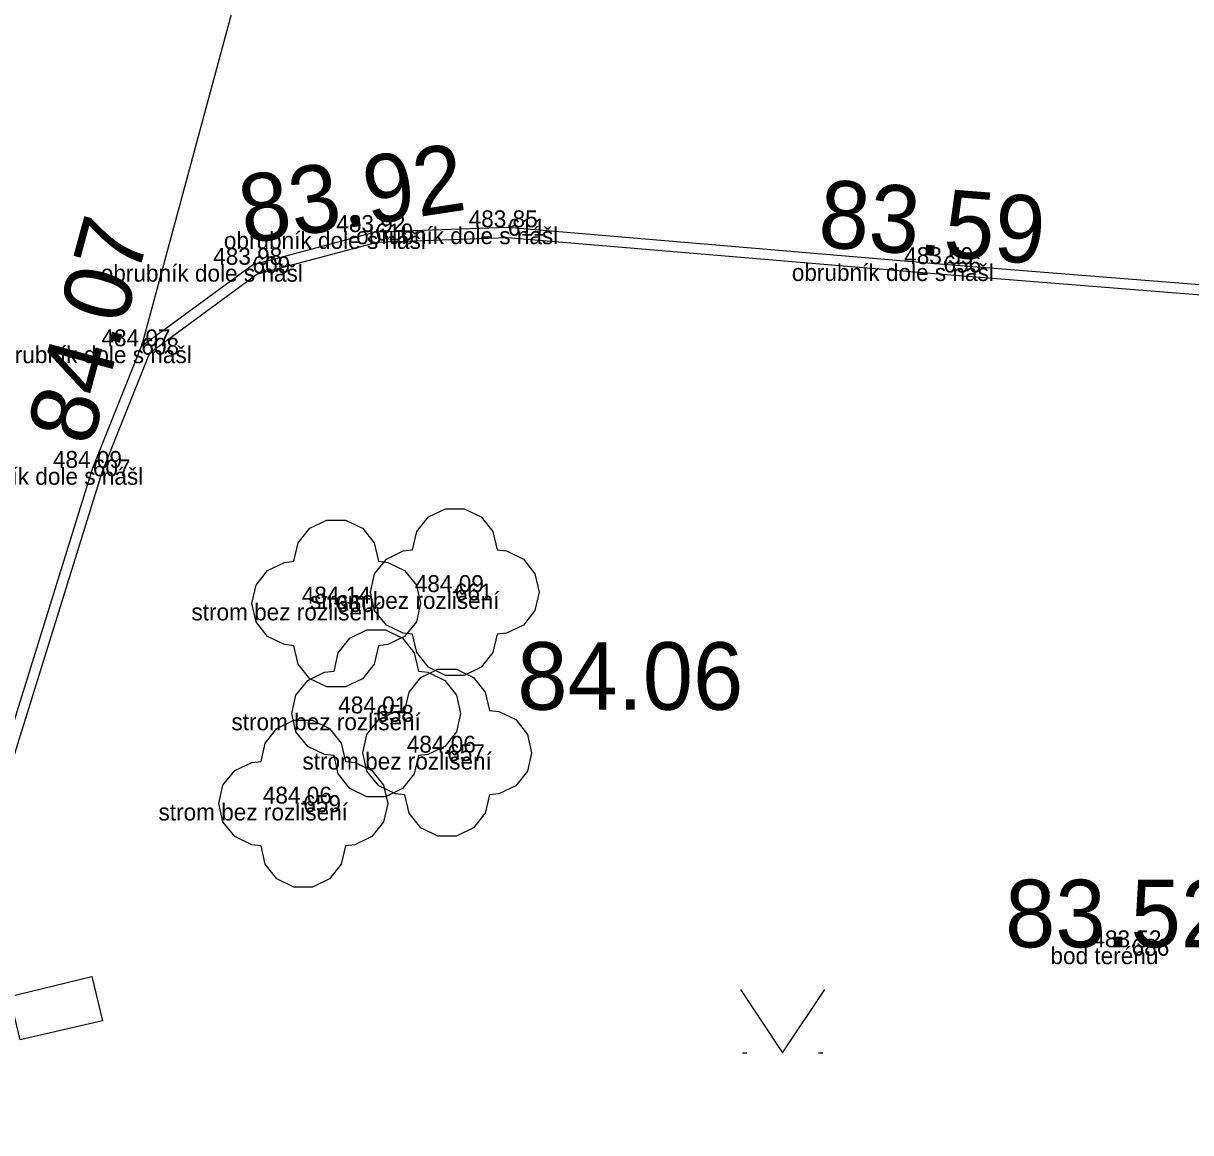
# Model space of a CAD drawing. Extents: x -888468 to -888310, y -1023047 to -1022832.
# Drawn here: x -888405.63 to -888391.81, y -1022946.43 to -1022933.29 of the extents above; entities that cross this region are included whole.
import ezdxf

# ---------------------------------------------------------------- set-up
doc = ezdxf.new("R2010")
doc.units = 0
for name, color, linetype in [('035-spod', 7, 'Continuous'), ('3 osa komunikace', 7, 'Continuous'), ('4 obrubník dole', 7, 'Continuous'), ('43 lampa', 7, 'Continuous'), ('60 strom bez rozlišení', 7, 'Continuous'), ('83 semafor', 7, 'Continuous'), ('bod', 7, 'Continuous'), ('bod kod', 7, 'Continuous'), ('bod výška', 7, 'Continuous'), ('bod číslo', 7, 'Continuous'), ('Implicitní', 7, 'Continuous'), ('KN stav', 7, 'Continuous'), ('Nadmořská výška TISK', 7, 'Continuous')]:
    doc.layers.add(name, color=color, linetype=linetype)

# ---------------------------------------------------------------- blocks, each defined once
blk = doc.blocks.new('314')
at = {"layer": 'Implicitní'}
for p, q in [((-9.5, 0), (-8.5, 0)), ((8.5, 0), (9.5, 0))]:
    blk.add_line(p, q, dxfattribs=at)
blk.add_lwpolyline([(-10, 15), (0, 0), (10, 15)], dxfattribs=at)

msp = doc.modelspace()

# ---------------------------------------------------------------- linework, layer by layer
at = {"layer": '035-spod'}
for p, q in [((-888399.894, -1022935.708), (-888399.894, -1022935.708)), ((-888399.894, -1022935.708), (-888399.894, -1022935.708)), ((-888399.894, -1022935.708), (-888399.894, -1022935.708)), ((-888399.894, -1022935.708), (-888399.894, -1022935.708)), ((-888401.462, -1022935.764), (-888401.462, -1022935.764)), ((-888401.462, -1022935.764), (-888401.462, -1022935.764)), ((-888401.462, -1022935.764), (-888401.462, -1022935.764)), ((-888401.462, -1022935.764), (-888401.462, -1022935.764)), ((-888402.92, -1022936.152), (-888402.92, -1022936.152)), ((-888402.92, -1022936.152), (-888402.92, -1022936.152)), ((-888402.92, -1022936.152), (-888402.92, -1022936.152)), ((-888402.92, -1022936.152), (-888402.92, -1022936.152)), ((-888394.734, -1022936.144), (-888394.734, -1022936.144)), ((-888394.734, -1022936.144), (-888394.734, -1022936.144)), ((-888394.734, -1022936.144), (-888394.734, -1022936.144)), ((-888394.734, -1022936.144), (-888394.734, -1022936.144)), ((-888404.236, -1022937.117), (-888404.236, -1022937.117)), ((-888404.236, -1022937.117), (-888404.236, -1022937.117)), ((-888404.236, -1022937.117), (-888404.236, -1022937.117)), ((-888404.236, -1022937.117), (-888404.236, -1022937.117)), ((-888404.81, -1022938.557), (-888404.81, -1022938.557)), ((-888404.81, -1022938.557), (-888404.81, -1022938.557)), ((-888404.81, -1022938.557), (-888404.81, -1022938.557)), ((-888404.81, -1022938.557), (-888404.81, -1022938.557)), ((-888400.523, -1022940.027), (-888400.523, -1022940.027)), ((-888400.523, -1022940.027), (-888400.523, -1022940.027)), ((-888400.523, -1022940.027), (-888400.523, -1022940.027)), ((-888400.523, -1022940.027), (-888400.523, -1022940.027)), ((-888401.928, -1022940.163), (-888401.928, -1022940.163)), ((-888401.928, -1022940.163), (-888401.928, -1022940.163)), ((-888401.928, -1022940.163), (-888401.928, -1022940.163)), ((-888401.928, -1022940.163), (-888401.928, -1022940.163)), ((-888401.454, -1022941.464), (-888401.454, -1022941.464)), ((-888401.454, -1022941.464), (-888401.454, -1022941.464)), ((-888401.454, -1022941.464), (-888401.454, -1022941.464)), ((-888401.454, -1022941.464), (-888401.454, -1022941.464)), ((-888400.613, -1022941.929), (-888400.613, -1022941.929)), ((-888400.613, -1022941.929), (-888400.613, -1022941.929)), ((-888400.613, -1022941.929), (-888400.613, -1022941.929)), ((-888400.613, -1022941.929), (-888400.613, -1022941.929)), ((-888402.318, -1022942.532), (-888402.318, -1022942.532)), ((-888402.318, -1022942.532), (-888402.318, -1022942.532)), ((-888402.318, -1022942.532), (-888402.318, -1022942.532)), ((-888402.318, -1022942.532), (-888402.318, -1022942.532)), ((-888392.505, -1022944.233), (-888392.505, -1022944.233)), ((-888392.505, -1022944.233), (-888392.505, -1022944.233)), ((-888392.505, -1022944.233), (-888392.505, -1022944.233)), ((-888392.505, -1022944.233), (-888392.505, -1022944.233))]:
    msp.add_line(p, q, dxfattribs=at)
at = {"layer": '3 osa komunikace'}
msp.add_lwpolyline([(-888400.291, -1022923.515), (-888402.634, -1022931.198), (-888404.236, -1022937.117)], dxfattribs=at)
at = {"layer": '4 obrubník dole'}
for points in [[(-888384.711, -1022952.853), (-888388.941, -1022951.975), (-888395.15, -1022950.69), (-888400.769, -1022949.547), (-888405.975, -1022948.361), (-888406.59, -1022947.266), (-888406.579, -1022945.304), (-888406.284, -1022943.285), (-888404.81, -1022938.557), (-888404.236, -1022937.117), (-888402.92, -1022936.152), (-888401.462, -1022935.764), (-888399.894, -1022935.708), (-888394.734, -1022936.144), (-888388.912, -1022936.608), (-888386.083, -1022936.393), (-888383.868, -1022935.673), (-888380.313, -1022934.038), (-888377.906, -1022932.303), (-888376.046, -1022930.543)], [(-888384.687, -1022952.736), (-888388.917, -1022951.857), (-888395.126, -1022950.572), (-888400.744, -1022949.43), (-888405.896, -1022948.256), (-888406.47, -1022947.235), (-888406.459, -1022945.313), (-888406.167, -1022943.312), (-888404.697, -1022938.597), (-888404.137, -1022937.193), (-888402.867, -1022936.262), (-888401.444, -1022935.883), (-888399.897, -1022935.828), (-888394.744, -1022936.264), (-888388.912, -1022936.728), (-888386.06, -1022936.512), (-888383.824, -1022935.785), (-888380.252, -1022934.142), (-888377.829, -1022932.396), (-888375.964, -1022930.63)]]:
    msp.add_lwpolyline(points, dxfattribs=at)
at = {"layer": '43 lampa'}
msp.add_lwpolyline([(-888406.271, -1022946.939), (-888406.196, -1022946.939), (-888406.071, -1022947.029), (-888406.021, -1022947.174), (-888406.071, -1022947.319), (-888406.196, -1022947.409), (-888406.351, -1022947.409), (-888406.476, -1022947.319), (-888406.526, -1022947.174), (-888406.476, -1022947.029), (-888406.351, -1022946.939), (-888406.271, -1022946.939), (-888406.271, -1022944.929), (-888404.821, -1022944.579), (-888404.696, -1022945.104), (-888405.671, -1022945.329), (-888405.796, -1022944.814)], dxfattribs=at)
at = {"layer": '60 strom bez rozlišení'}
for points in [[(-888399.523, -1022940.027), (-888399.573, -1022940.244), (-888399.711, -1022940.418), (-888399.912, -1022940.515), (-888400.023, -1022940.527), (-888400.073, -1022940.744), (-888400.211, -1022940.918), (-888400.412, -1022941.015), (-888400.634, -1022941.015), (-888400.834, -1022940.918), (-888400.973, -1022940.744), (-888401.023, -1022940.527), (-888401.134, -1022940.515), (-888401.334, -1022940.418), (-888401.473, -1022940.244), (-888401.523, -1022940.027), (-888401.473, -1022939.81), (-888401.334, -1022939.636), (-888401.134, -1022939.54), (-888401.023, -1022939.527), (-888400.973, -1022939.31), (-888400.834, -1022939.136), (-888400.634, -1022939.04), (-888400.412, -1022939.04), (-888400.211, -1022939.136), (-888400.073, -1022939.31), (-888400.023, -1022939.527), (-888399.912, -1022939.54), (-888399.711, -1022939.636), (-888399.573, -1022939.81)], [(-888400.928, -1022940.163), (-888400.978, -1022940.38), (-888401.117, -1022940.554), (-888401.317, -1022940.65), (-888401.428, -1022940.663), (-888401.478, -1022940.88), (-888401.617, -1022941.054), (-888401.817, -1022941.15), (-888402.039, -1022941.15), (-888402.24, -1022941.054), (-888402.378, -1022940.88), (-888402.428, -1022940.663), (-888402.539, -1022940.65), (-888402.74, -1022940.554), (-888402.878, -1022940.38), (-888402.928, -1022940.163), (-888402.878, -1022939.946), (-888402.74, -1022939.772), (-888402.539, -1022939.676), (-888402.428, -1022939.663), (-888402.378, -1022939.446), (-888402.24, -1022939.272), (-888402.039, -1022939.176), (-888401.817, -1022939.176), (-888401.617, -1022939.272), (-888401.478, -1022939.446), (-888401.428, -1022939.663), (-888401.317, -1022939.676), (-888401.117, -1022939.772), (-888400.978, -1022939.946)], [(-888400.454, -1022941.464), (-888400.503, -1022941.681), (-888400.643, -1022941.855), (-888400.843, -1022941.951), (-888400.954, -1022941.964), (-888401.003, -1022942.181), (-888401.143, -1022942.355), (-888401.343, -1022942.451), (-888401.565, -1022942.451), (-888401.765, -1022942.355), (-888401.905, -1022942.181), (-888401.954, -1022941.964), (-888402.065, -1022941.951), (-888402.265, -1022941.855), (-888402.405, -1022941.681), (-888402.454, -1022941.464), (-888402.405, -1022941.247), (-888402.265, -1022941.073), (-888402.065, -1022940.976), (-888401.954, -1022940.964), (-888401.905, -1022940.747), (-888401.765, -1022940.573), (-888401.565, -1022940.476), (-888401.343, -1022940.476), (-888401.143, -1022940.573), (-888401.003, -1022940.747), (-888400.954, -1022940.964), (-888400.843, -1022940.976), (-888400.643, -1022941.073), (-888400.503, -1022941.247)], [(-888399.613, -1022941.929), (-888399.662, -1022942.146), (-888399.802, -1022942.32), (-888400.002, -1022942.417), (-888400.113, -1022942.429), (-888400.162, -1022942.646), (-888400.302, -1022942.82), (-888400.502, -1022942.917), (-888400.724, -1022942.917), (-888400.924, -1022942.82), (-888401.064, -1022942.646), (-888401.113, -1022942.429), (-888401.224, -1022942.417), (-888401.424, -1022942.32), (-888401.564, -1022942.146), (-888401.613, -1022941.929), (-888401.564, -1022941.712), (-888401.424, -1022941.538), (-888401.224, -1022941.442), (-888401.113, -1022941.429), (-888401.064, -1022941.212), (-888400.924, -1022941.038), (-888400.724, -1022940.942), (-888400.502, -1022940.942), (-888400.302, -1022941.038), (-888400.162, -1022941.212), (-888400.113, -1022941.429), (-888400.002, -1022941.442), (-888399.802, -1022941.538), (-888399.662, -1022941.712)], [(-888401.318, -1022942.532), (-888401.368, -1022942.749), (-888401.507, -1022942.923), (-888401.707, -1022943.02), (-888401.818, -1022943.032), (-888401.868, -1022943.249), (-888402.007, -1022943.423), (-888402.207, -1022943.52), (-888402.429, -1022943.52), (-888402.63, -1022943.423), (-888402.769, -1022943.249), (-888402.818, -1022943.032), (-888402.929, -1022943.02), (-888403.13, -1022942.923), (-888403.269, -1022942.749), (-888403.318, -1022942.532), (-888403.269, -1022942.315), (-888403.13, -1022942.141), (-888402.929, -1022942.045), (-888402.818, -1022942.032), (-888402.769, -1022941.815), (-888402.63, -1022941.641), (-888402.429, -1022941.545), (-888402.207, -1022941.545), (-888402.007, -1022941.641), (-888401.868, -1022941.815), (-888401.818, -1022942.032), (-888401.707, -1022942.045), (-888401.507, -1022942.141), (-888401.368, -1022942.315)]]:
    msp.add_lwpolyline(points, close=True, dxfattribs=at)
for points in [[(-888400.548, -1022940.027), (-888400.523, -1022940.027), (-888400.498, -1022940.027)], [(-888401.953, -1022940.163), (-888401.928, -1022940.163), (-888401.903, -1022940.163)], [(-888401.479, -1022941.464), (-888401.454, -1022941.464), (-888401.429, -1022941.464)], [(-888400.638, -1022941.929), (-888400.613, -1022941.929), (-888400.588, -1022941.929)], [(-888402.343, -1022942.532), (-888402.318, -1022942.532), (-888402.293, -1022942.532)]]:
    msp.add_lwpolyline(points, dxfattribs=at)
at = {"layer": '83 semafor'}
for p, q in [((-888399.894, -1022935.708), (-888399.894, -1022935.708)), ((-888401.462, -1022935.764), (-888401.462, -1022935.764)), ((-888402.92, -1022936.152), (-888402.92, -1022936.152)), ((-888394.734, -1022936.144), (-888394.734, -1022936.144)), ((-888404.236, -1022937.117), (-888404.236, -1022937.117)), ((-888404.81, -1022938.557), (-888404.81, -1022938.557)), ((-888400.523, -1022940.027), (-888400.523, -1022940.027)), ((-888401.928, -1022940.163), (-888401.928, -1022940.163)), ((-888401.454, -1022941.464), (-888401.454, -1022941.464)), ((-888400.613, -1022941.929), (-888400.613, -1022941.929)), ((-888402.318, -1022942.532), (-888402.318, -1022942.532)), ((-888392.505, -1022944.233), (-888392.505, -1022944.233))]:
    msp.add_line(p, q, dxfattribs=at)
at = {"layer": 'bod'}
for p, q in [((-888399.894, -1022935.708), (-888399.894, -1022935.708)), ((-888401.462, -1022935.764), (-888401.462, -1022935.764)), ((-888402.92, -1022936.152), (-888402.92, -1022936.152)), ((-888394.734, -1022936.144), (-888394.734, -1022936.144)), ((-888404.236, -1022937.117), (-888404.236, -1022937.117)), ((-888404.81, -1022938.557), (-888404.81, -1022938.557)), ((-888400.523, -1022940.027), (-888400.523, -1022940.027)), ((-888401.928, -1022940.163), (-888401.928, -1022940.163)), ((-888401.454, -1022941.464), (-888401.454, -1022941.464)), ((-888400.613, -1022941.929), (-888400.613, -1022941.929)), ((-888402.318, -1022942.532), (-888402.318, -1022942.532)), ((-888392.505, -1022944.233), (-888392.505, -1022944.233))]:
    msp.add_line(p, q, dxfattribs=at)

# ---------------------------------------------------------------- block references
at = {"layer": 'KN stav', "xscale": 0.05, "yscale": 0.05000000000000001}
msp.add_blockref('314', (-888396.64, -1022945.484), dxfattribs=at)

# ---------------------------------------------------------------- texts
at = {"layer": 'bod kod'}
for s, p in [('obrubník dole s nášl', (-888403.259, -1022935.964)), ('obrubník dole s nášl', (-888401.691, -1022935.908)), ('obrubník dole s nášl', (-888404.717, -1022936.352)), ('obrubník dole s nášl', (-888396.531, -1022936.344)), ('obrubník dole s nášl', (-888406.033, -1022937.317)), ('obrubník dole s nášl', (-888406.607, -1022938.757)), ('strom bez rozlišení', (-888402.238, -1022940.227)), ('strom bez rozlišení', (-888403.643, -1022940.363)), ('strom bez rozlišení', (-888403.169, -1022941.664)), ('strom bez rozlišení', (-888402.328, -1022942.129)), ('strom bez rozlišení', (-888404.033, -1022942.732)), ('bod terénu', (-888393.467, -1022944.433))]:
    msp.add_text(s, height=0.2, dxfattribs=at).set_placement(p)
at = {"layer": 'bod výška'}
for s, p in [('483.92', (-888401.927, -1022935.764)), ('483.85', (-888400.359, -1022935.708)), ('483.98', (-888403.385, -1022936.152)), ('483.59', (-888395.199, -1022936.144)), ('484.07', (-888404.709, -1022937.117)), ('484.09', (-888405.284, -1022938.557)), ('484.09', (-888400.997, -1022940.027)), ('484.14', (-888402.336, -1022940.163)), ('484.01', (-888401.904, -1022941.464)), ('484.06', (-888401.092, -1022941.929)), ('484.06', (-888402.797, -1022942.532)), ('483.52', (-888392.97, -1022944.233))]:
    msp.add_text(s, height=0.2, dxfattribs=at).set_placement(p)
at = {"layer": 'bod číslo'}
for s, p in [('611', (-888399.894, -1022935.808)), ('610', (-888401.462, -1022935.864)), ('609', (-888402.92, -1022936.252)), ('656', (-888394.734, -1022936.244)), ('608', (-888404.236, -1022937.217)), ('607', (-888404.81, -1022938.657)), ('661', (-888400.523, -1022940.127)), ('660', (-888401.928, -1022940.263)), ('658', (-888401.454, -1022941.564)), ('657', (-888400.613, -1022942.029)), ('659', (-888402.318, -1022942.632)), ('686', (-888392.505, -1022944.333))]:
    msp.add_text(s, height=0.2, dxfattribs=at).set_placement(p)
at = {"layer": 'Nadmořská výška TISK'}
for s, rotation, p in [('83.92', 8.7643, (-888403.01, -1022935.904)), ('83.59', 355.4692, (-888396.232, -1022935.937)), ('84.07', 74.7523, (-888404.83, -1022938.318))]:
    msp.add_text(s, height=0.8, rotation=rotation, dxfattribs=at).set_placement(p)
for s, p in [('84.06', (-888399.783, -1022941.421)), ('83.52', (-888394.004, -1022944.233))]:
    msp.add_text(s, height=0.8, dxfattribs=at).set_placement(p)

doc.saveas('drawing.dxf')
